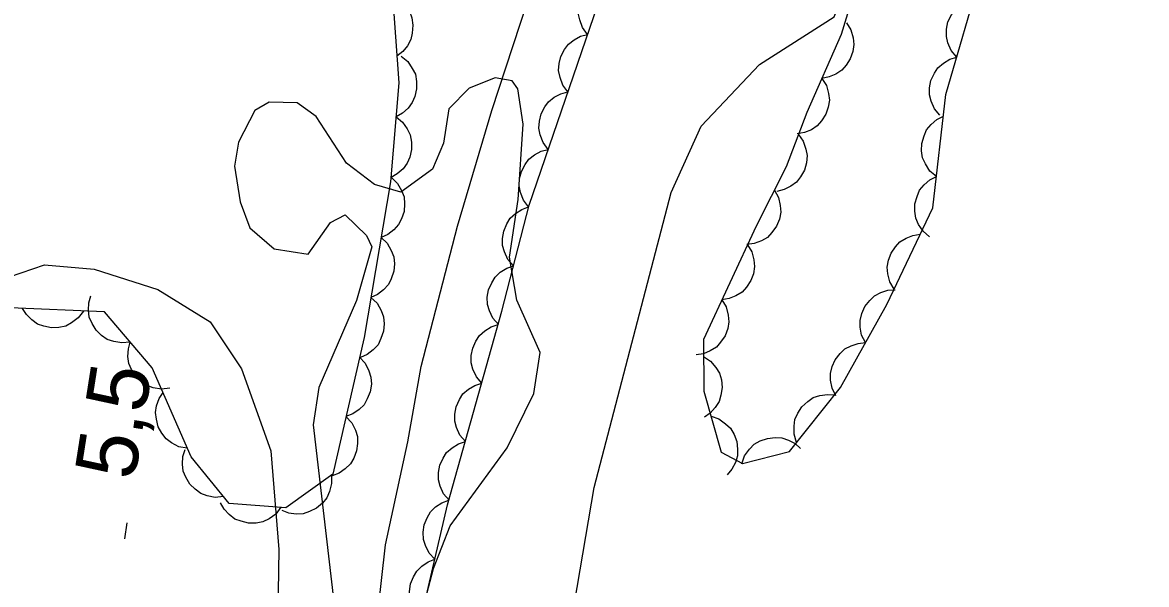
# Model space of a CAD drawing. Extents: x 282461 to 284471, y 5554090 to 5557646.
# Drawn here: x 283662.4 to 283717.9, y 5555137.6 to 5555165.4 of the extents above; entities that cross this region are included whole.
import ezdxf

# ---------------------------------------------------------------- set-up
doc = ezdxf.new("R2010")
doc.units = 0
for name, color, linetype in [('Niveau 1', 7, 'Continuous'), ('Niveau 2', 7, 'Continuous'), ('Niveau 22', 7, 'Continuous'), ('Niveau 3', 7, 'Continuous'), ('Niveau 44', 7, 'Continuous')]:
    doc.layers.add(name, color=color, linetype=linetype)

msp = doc.modelspace()

# ---------------------------------------------------------------- linework, layer by layer
at = {"layer": 'Niveau 1'}
for points in [[(283689.65, 5555136.73), (283690.63, 5555142.42), (283694.42, 5555156.97), (283695.9, 5555160.24), (283698.78, 5555163.28), (283702.47, 5555165.64), (283703.38, 5555167.97), (283702.41, 5555171.1), (283701.9, 5555174.69), (283701.74, 5555179.22), (283703.15, 5555187.94), (283706.09, 5555195.28), (283708.71, 5555200.76), (283710.75, 5555205.31), (283711.03, 5555208.4)], [(283635.3, 5555136.76), (283637.97, 5555137.95), (283642.85, 5555138.35), (283648.99, 5555140.5), (283651.18, 5555142.03), (283654.17, 5555145.42), (283656.12, 5555147.88), (283657.84, 5555149.75), (283659.92, 5555151.52), (283661.77, 5555152.81), (283663.5, 5555153.41), (283665.95, 5555153.2), (283669.1, 5555152.19), (283671.68, 5555150.59), (283673.22, 5555148.28), (283674.67, 5555144.24), (283675.07, 5555139.37), (283674.93, 5555131.01)]]:
    msp.add_lwpolyline(points, dxfattribs=at)
at = {"layer": 'Niveau 2'}
for points in [[(283681, 5555132.01), (283682.69, 5555138.44), (283683.51, 5555140.53), (283686.33, 5555144.38), (283687.65, 5555147.07), (283687.95, 5555149.09), (283686.8, 5555151.67), (283686.44, 5555153.78), (283686.87, 5555156.62), (283687.12, 5555160.35), (283686.86, 5555162.09), (283686.57, 5555162.48), (283685.74, 5555162.62), (283684.46, 5555162.12), (283683.45, 5555161.09), (283683.19, 5555159.4), (283682.64, 5555158.12), (283681.09, 5555156.99), (283679.78, 5555157.36), (283678.4, 5555158.42), (283676.9, 5555160.72), (283675.96, 5555161.39), (283674.59, 5555161.43), (283673.88, 5555161.02), (283673.07, 5555159.46), (283672.88, 5555158.27), (283673.15, 5555156.51), (283673.63, 5555155.23), (283674.84, 5555154.2), (283676.51, 5555153.93), (283677.62, 5555155.49), (283678.34, 5555155.87), (283679.39, 5555154.86), (283679.65, 5555154.29), (283678.9, 5555151.65)], [(283678.9, 5555151.65), (283677.03, 5555147.36), (283676.76, 5555145.51), (283677.78, 5555136.79)]]:
    msp.add_lwpolyline(points, dxfattribs=at)
at = {"layer": 'Niveau 22'}
msp.add_lwpolyline([(283679.71, 5555134.18), (283680.33, 5555139.6), (283681.43, 5555144.68), (283682.09, 5555148.4), (283683.88, 5555155.31), (283685.57, 5555161.01), (283687.67, 5555167.44), (283688.99, 5555170.38), (283691.07, 5555175.94), (283692.01, 5555179.06), (283693.42, 5555182.46), (283696.09, 5555192.45), (283696.93, 5555195.13), (283698.18, 5555198.46), (283700.83, 5555204.74), (283706.24, 5555216.69), (283707.09, 5555218.85), (283708.95, 5555224.04), (283710.85, 5555231.15), (283711.78, 5555236.68), (283712.45, 5555239.36), (283712.77, 5555242.09), (283713.32, 5555245.38)], dxfattribs=at)
at = {"layer": 'Niveau 3'}
msp.add_line((283667.46, 5555139.89), (283667.58, 5555140.68), dxfattribs=at)
at = {"layer": 'Niveau 44'}
for points in [[(283678.75, 5555121.66), (283683.39, 5555141.57), (283686.07, 5555151.12), (283687.41, 5555156.35), (283693.6, 5555174.4), (283695.87, 5555179.65), (283698.83, 5555185.72), (283703.25, 5555195.86), (283706.89, 5555203.33), (283713.15, 5555217.86), (283716.75, 5555228.38), (283718.59, 5555234.03), (283719.23, 5555237.1), (283719.73, 5555243.52), (283720.03, 5555244.88)], [(283685.82, 5555207.92), (283684.24, 5555203.95), (283682.88, 5555201.16), (283681.06, 5555196.73), (283680.65, 5555192.54), (283681.39, 5555188.14), (283682.13, 5555184.9), (283682.16, 5555182.12), (283681.72, 5555179.79), (283681.04, 5555178.16), (283680.16, 5555173.74), (283680.99, 5555162.38), (283680.58, 5555157.5), (283679.27, 5555149.83), (283677.72, 5555143.08), (283675.41, 5555141.43), (283672.62, 5555141.64), (283670.73, 5555143.94), (283668.82, 5555148.33), (283666.46, 5555151.09), (283661.8, 5555151.28)], [(283704.16, 5555169.18), (283702.81, 5555164.76), (283701.11, 5555160.92), (283700.1, 5555158.24), (283698.62, 5555155.32), (283696.01, 5555149.73), (283696.04, 5555147.18), (283696.88, 5555144.17), (283697.94, 5555143.61), (283700.26, 5555144.21), (283702.78, 5555147.36), (283705.06, 5555151.45), (283707.33, 5555156.22), (283707.97, 5555161.8), (283709.76, 5555167.96)], [(283690.3, 5555164.77), (283690.05, 5555165.11), (283689.91, 5555165.49), (283689.84, 5555165.81), (283689.86, 5555166.16), (283689.95, 5555166.52), (283690.13, 5555166.86), (283690.32, 5555167.12), (283690.6, 5555167.34), (283690.92, 5555167.52), (283691.27, 5555167.61)], [(283680.68, 5555166.69), (283681.04, 5555166.48), (283681.32, 5555166.18), (283681.51, 5555165.91), (283681.62, 5555165.58), (283681.68, 5555165.22), (283681.64, 5555164.83), (283681.58, 5555164.51), (283681.41, 5555164.21), (283681.18, 5555163.92), (283680.89, 5555163.69)], [(283708.51, 5555163.65), (283708.24, 5555163.98), (283708.08, 5555164.35), (283708, 5555164.67), (283708.01, 5555165.02), (283708.08, 5555165.38), (283708.25, 5555165.73), (283708.42, 5555166), (283708.69, 5555166.23), (283709, 5555166.42), (283709.35, 5555166.53)], [(283703.07, 5555165.34), (283703.29, 5555164.99), (283703.4, 5555164.6), (283703.44, 5555164.27), (283703.38, 5555163.92), (283703.26, 5555163.57), (283703.05, 5555163.25), (283702.85, 5555163), (283702.55, 5555162.81), (283702.21, 5555162.67), (283701.85, 5555162.6)], [(283689.33, 5555161.94), (283689.08, 5555162.27), (283688.94, 5555162.65), (283688.86, 5555162.98), (283688.89, 5555163.33), (283688.98, 5555163.68), (283689.16, 5555164.02), (283689.35, 5555164.29), (283689.63, 5555164.5), (283689.95, 5555164.68), (283690.3, 5555164.77)], [(283681.1, 5555163.69), (283681.43, 5555163.43), (283681.65, 5555163.09), (283681.8, 5555162.8), (283681.86, 5555162.45), (283681.86, 5555162.08), (283681.77, 5555161.71), (283681.65, 5555161.41), (283681.44, 5555161.13), (283681.16, 5555160.88), (283680.85, 5555160.7)], [(283707.67, 5555160.78), (283707.41, 5555161.1), (283707.25, 5555161.47), (283707.16, 5555161.79), (283707.17, 5555162.14), (283707.24, 5555162.5), (283707.41, 5555162.85), (283707.58, 5555163.12), (283707.85, 5555163.35), (283708.17, 5555163.54), (283708.51, 5555163.65)], [(283701.85, 5555162.6), (283702.08, 5555162.25), (283702.18, 5555161.86), (283702.23, 5555161.53), (283702.17, 5555161.18), (283702.05, 5555160.83), (283701.84, 5555160.51), (283701.63, 5555160.26), (283701.34, 5555160.07), (283701, 5555159.93), (283700.64, 5555159.86)], [(283688.35, 5555159.1), (283688.1, 5555159.44), (283687.96, 5555159.82), (283687.89, 5555160.14), (283687.92, 5555160.49), (283688.01, 5555160.85), (283688.19, 5555161.19), (283688.37, 5555161.45), (283688.65, 5555161.67), (283688.98, 5555161.84), (283689.33, 5555161.94)], [(283680.85, 5555160.7), (283681.17, 5555160.44), (283681.4, 5555160.11), (283681.55, 5555159.81), (283681.61, 5555159.46), (283681.61, 5555159.09), (283681.52, 5555158.72), (283681.4, 5555158.42), (283681.19, 5555158.14), (283680.91, 5555157.89), (283680.6, 5555157.71)], [(283707.51, 5555157.76), (283707.19, 5555158.03), (283706.97, 5555158.38), (283706.83, 5555158.68), (283706.78, 5555159.02), (283706.79, 5555159.39), (283706.9, 5555159.76), (283707.02, 5555160.06), (283707.25, 5555160.33), (283707.53, 5555160.57), (283707.85, 5555160.74)], [(283700.7, 5555159.84), (283700.94, 5555159.5), (283701.07, 5555159.11), (283701.13, 5555158.79), (283701.1, 5555158.44), (283701, 5555158.08), (283700.8, 5555157.75), (283700.61, 5555157.49), (283700.33, 5555157.28), (283699.99, 5555157.12), (283699.64, 5555157.03)], [(283687.38, 5555156.27), (283687.13, 5555156.6), (283686.99, 5555156.98), (283686.92, 5555157.3), (283686.94, 5555157.66), (283687.03, 5555158.01), (283687.22, 5555158.35), (283687.4, 5555158.62), (283687.68, 5555158.83), (283688.01, 5555159.01), (283688.35, 5555159.1)], [(283680.62, 5555157.71), (283680.92, 5555157.42), (283681.12, 5555157.07), (283681.24, 5555156.76), (283681.27, 5555156.41), (283681.24, 5555156.04), (283681.11, 5555155.68), (283680.97, 5555155.39), (283680.73, 5555155.13), (283680.44, 5555154.9), (283680.11, 5555154.76)], [(283707.17, 5555154.78), (283706.85, 5555155.06), (283706.63, 5555155.4), (283706.49, 5555155.7), (283706.44, 5555156.05), (283706.45, 5555156.41), (283706.56, 5555156.78), (283706.68, 5555157.08), (283706.91, 5555157.35), (283707.19, 5555157.6), (283707.51, 5555157.76)], [(283699.52, 5555157.09), (283699.72, 5555156.72), (283699.8, 5555156.33), (283699.83, 5555156), (283699.76, 5555155.65), (283699.62, 5555155.31), (283699.39, 5555155), (283699.17, 5555154.76), (283698.87, 5555154.59), (283698.52, 5555154.46), (283698.16, 5555154.41)], [(283686.64, 5555153.36), (283686.37, 5555153.67), (283686.2, 5555154.04), (283686.1, 5555154.36), (283686.1, 5555154.71), (283686.16, 5555155.07), (283686.31, 5555155.42), (283686.48, 5555155.71), (283686.74, 5555155.94), (283687.05, 5555156.14), (283687.39, 5555156.27)], [(283705.42, 5555152.21), (283705.21, 5555152.57), (283705.11, 5555152.96), (283705.08, 5555153.29), (283705.14, 5555153.64), (283705.27, 5555153.98), (283705.49, 5555154.3), (283705.71, 5555154.54), (283706.01, 5555154.72), (283706.35, 5555154.86), (283706.71, 5555154.92)], [(283680.11, 5555154.76), (283680.41, 5555154.47), (283680.61, 5555154.11), (283680.73, 5555153.8), (283680.77, 5555153.45), (283680.74, 5555153.09), (283680.61, 5555152.72), (283680.47, 5555152.43), (283680.23, 5555152.17), (283679.93, 5555151.95), (283679.61, 5555151.8)], [(283698.19, 5555154.4), (283698.4, 5555154.04), (283698.5, 5555153.65), (283698.54, 5555153.32), (283698.48, 5555152.97), (283698.35, 5555152.63), (283698.13, 5555152.31), (283697.92, 5555152.06), (283697.62, 5555151.88), (283697.28, 5555151.74), (283696.92, 5555151.68)], [(283685.9, 5555150.46), (283685.62, 5555150.77), (283685.45, 5555151.14), (283685.36, 5555151.45), (283685.35, 5555151.81), (283685.41, 5555152.17), (283685.57, 5555152.52), (283685.73, 5555152.8), (283685.99, 5555153.04), (283686.31, 5555153.24), (283686.64, 5555153.36)], [(283704.01, 5555149.57), (283703.82, 5555149.94), (283703.75, 5555150.34), (283703.74, 5555150.67), (283703.83, 5555151.01), (283703.98, 5555151.35), (283704.22, 5555151.64), (283704.45, 5555151.88), (283704.76, 5555152.04), (283705.11, 5555152.15), (283705.47, 5555152.18)], [(283667.73, 5555149.6), (283667.32, 5555149.56), (283666.92, 5555149.63), (283666.6, 5555149.73), (283666.31, 5555149.93), (283666.05, 5555150.19), (283665.85, 5555150.52), (283665.71, 5555150.82), (283665.67, 5555151.17), (283665.69, 5555151.54), (283665.78, 5555151.88)], [(283679.61, 5555151.8), (283679.91, 5555151.51), (283680.11, 5555151.15), (283680.23, 5555150.85), (283680.26, 5555150.5), (283680.23, 5555150.13), (283680.1, 5555149.77), (283679.96, 5555149.47), (283679.72, 5555149.22), (283679.43, 5555148.99), (283679.1, 5555148.84)], [(283696.92, 5555151.68), (283697.14, 5555151.33), (283697.23, 5555150.93), (283697.27, 5555150.6), (283697.21, 5555150.26), (283697.08, 5555149.91), (283696.86, 5555149.6), (283696.65, 5555149.35), (283696.35, 5555149.16), (283696.01, 5555149.02), (283695.65, 5555148.97)], [(283665.42, 5555151.13), (283665.17, 5555150.8), (283664.84, 5555150.55), (283664.55, 5555150.39), (283664.21, 5555150.32), (283663.84, 5555150.3), (283663.47, 5555150.38), (283663.16, 5555150.48), (283662.87, 5555150.69), (283662.61, 5555150.95), (283662.42, 5555151.25)], [(283685.08, 5555147.58), (283684.81, 5555147.89), (283684.64, 5555148.27), (283684.56, 5555148.58), (283684.56, 5555148.94), (283684.63, 5555149.3), (283684.79, 5555149.65), (283684.96, 5555149.92), (283685.23, 5555150.15), (283685.54, 5555150.35), (283685.89, 5555150.46)], [(283669.68, 5555147.32), (283669.27, 5555147.28), (283668.87, 5555147.35), (283668.55, 5555147.45), (283668.26, 5555147.65), (283668, 5555147.91), (283667.8, 5555148.24), (283667.66, 5555148.54), (283667.62, 5555148.89), (283667.64, 5555149.26), (283667.73, 5555149.6)], [(283702.55, 5555146.95), (283702.36, 5555147.32), (283702.29, 5555147.72), (283702.28, 5555148.05), (283702.37, 5555148.39), (283702.52, 5555148.73), (283702.76, 5555149.03), (283702.99, 5555149.26), (283703.3, 5555149.42), (283703.65, 5555149.53), (283704.01, 5555149.57)], [(283679.05, 5555148.85), (283679.33, 5555148.55), (283679.51, 5555148.18), (283679.61, 5555147.87), (283679.63, 5555147.52), (283679.57, 5555147.15), (283679.43, 5555146.8), (283679.27, 5555146.51), (283679.02, 5555146.27), (283678.71, 5555146.06), (283678.37, 5555145.93)], [(283696.02, 5555148.89), (283696.37, 5555148.66), (283696.63, 5555148.35), (283696.8, 5555148.07), (283696.9, 5555147.73), (283696.93, 5555147.36), (283696.87, 5555146.98), (283696.79, 5555146.67), (283696.6, 5555146.37), (283696.35, 5555146.1), (283696.06, 5555145.89)], [(283684.27, 5555144.69), (283684, 5555145.01), (283683.83, 5555145.38), (283683.75, 5555145.7), (283683.75, 5555146.05), (283683.82, 5555146.41), (283683.98, 5555146.76), (283684.15, 5555147.04), (283684.42, 5555147.27), (283684.73, 5555147.46), (283685.08, 5555147.58)], [(283670.54, 5555144.37), (283670.13, 5555144.44), (283669.77, 5555144.63), (283669.5, 5555144.82), (283669.29, 5555145.1), (283669.11, 5555145.42), (283669.02, 5555145.79), (283668.97, 5555146.12), (283669.03, 5555146.46), (283669.16, 5555146.81), (283669.35, 5555147.12)], [(283700.61, 5555144.65), (283700.49, 5555145.05), (283700.49, 5555145.45), (283700.53, 5555145.78), (283700.67, 5555146.1), (283700.87, 5555146.41), (283701.16, 5555146.67), (283701.42, 5555146.86), (283701.76, 5555146.96), (283702.13, 5555147.02), (283702.48, 5555146.99)], [(283678.37, 5555145.93), (283678.66, 5555145.62), (283678.84, 5555145.26), (283678.94, 5555144.94), (283678.95, 5555144.59), (283678.9, 5555144.23), (283678.76, 5555143.87), (283678.6, 5555143.59), (283678.34, 5555143.34), (283678.04, 5555143.13), (283677.7, 5555143)], [(283696.39, 5555145.94), (283696.78, 5555145.81), (283697.11, 5555145.57), (283697.35, 5555145.35), (283697.53, 5555145.04), (283697.66, 5555144.7), (283697.7, 5555144.32), (283697.7, 5555143.99), (283697.59, 5555143.66), (283697.42, 5555143.33), (283697.19, 5555143.05)], [(283697.9, 5555143.6), (283698.04, 5555143.99), (283698.28, 5555144.32), (283698.51, 5555144.56), (283698.82, 5555144.73), (283699.17, 5555144.85), (283699.55, 5555144.89), (283699.88, 5555144.88), (283700.21, 5555144.76), (283700.54, 5555144.59), (283700.81, 5555144.35)], [(283672.34, 5555141.98), (283671.92, 5555141.94), (283671.53, 5555142.02), (283671.21, 5555142.13), (283670.93, 5555142.34), (283670.67, 5555142.6), (283670.48, 5555142.93), (283670.35, 5555143.23), (283670.31, 5555143.58), (283670.33, 5555143.95), (283670.44, 5555144.3)], [(283683.46, 5555141.8), (283683.19, 5555142.12), (283683.02, 5555142.5), (283682.94, 5555142.81), (283682.94, 5555143.16), (283683.01, 5555143.53), (283683.17, 5555143.87), (283683.34, 5555144.15), (283683.61, 5555144.38), (283683.92, 5555144.58), (283684.27, 5555144.69)], [(283677.66, 5555143.03), (283677.67, 5555142.62), (283677.56, 5555142.23), (283677.43, 5555141.92), (283677.21, 5555141.65), (283676.92, 5555141.41), (283676.58, 5555141.24), (283676.27, 5555141.13), (283675.92, 5555141.12), (283675.55, 5555141.17), (283675.22, 5555141.29)], [(283675.17, 5555141.45), (283674.91, 5555141.12), (283674.58, 5555140.89), (283674.28, 5555140.74), (283673.94, 5555140.67), (283673.57, 5555140.67), (283673.2, 5555140.76), (283672.89, 5555140.87), (283672.61, 5555141.09), (283672.36, 5555141.36), (283672.18, 5555141.67)], [(283682.76, 5555138.89), (283682.48, 5555139.19), (283682.3, 5555139.56), (283682.2, 5555139.87), (283682.19, 5555140.22), (283682.24, 5555140.59), (283682.39, 5555140.94), (283682.55, 5555141.23), (283682.8, 5555141.47), (283683.11, 5555141.68), (283683.45, 5555141.81)], [(283682.08, 5555135.97), (283681.8, 5555136.27), (283681.62, 5555136.64), (283681.52, 5555136.95), (283681.51, 5555137.3), (283681.56, 5555137.67), (283681.71, 5555138.02), (283681.87, 5555138.31), (283682.12, 5555138.55), (283682.43, 5555138.76), (283682.76, 5555138.89)]]:
    msp.add_lwpolyline(points, dxfattribs=at)

# ---------------------------------------------------------------- texts
at = {"layer": 'Niveau 3'}
msp.add_text('5,5  ', height=3, rotation=81.0957, dxfattribs=at).set_placement((283667.94, 5555142.73))

doc.saveas('drawing.dxf')
